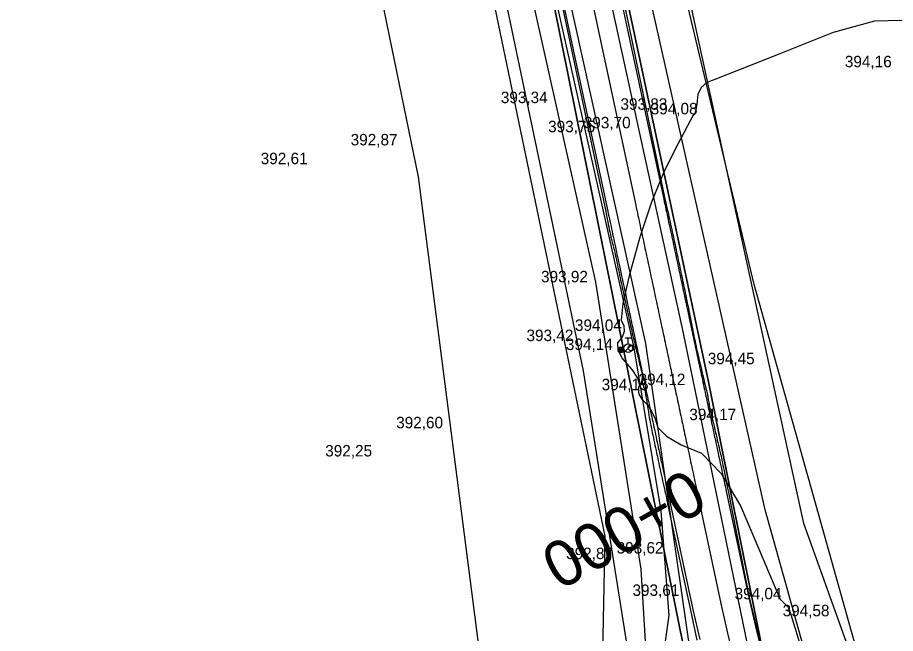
# Model space of a CAD drawing. Extents: x -574342 to -507939, y -1144044 to -1123894.
# Drawn here: x -508564.2 to -508487.6, y -1143040.7 to -1142986.9 of the extents above; entities that cross this region are included whole.
import ezdxf

# ---------------------------------------------------------------- set-up
doc = ezdxf.new("R2010")
doc.units = 0
for name, color, linetype in [('01_PARCELY_NAVRH_PC', 7, 'Continuous'), ('01_PARCELY_NAVRH_ŽP', 7, 'Continuous'), ('07_VODOVOD', 7, 'Continuous'), ('1000', 7, 'Continuous'), ('18', 7, 'Continuous'), ('21', 7, 'Continuous'), ('37', 7, 'Continuous'), ('42', 7, 'Continuous'), ('52', 7, 'Continuous'), ('55', 7, 'Continuous'), ('6', 7, 'Continuous'), ('Level 255', 7, 'Continuous'), ('VRST VEDL', 7, 'Continuous')]:
    doc.layers.add(name, color=color, linetype=linetype)

msp = doc.modelspace()

# ---------------------------------------------------------------- linework, layer by layer
at = {"layer": '01_PARCELY_NAVRH_PC'}
msp.add_lwpolyline([(-508546.584, -1142847.7), (-508527.76, -1142936.34), (-508528.85, -1142941.84), (-508524.62, -1142962.65), (-508521.23, -1142966.97), (-508506.03, -1143042.25), (-508499.26, -1143041.98), (-508503.94, -1143018.7), (-508540.355, -1142847.7)], dxfattribs=at)
at = {"layer": '01_PARCELY_NAVRH_ŽP'}
for points in [[(-508551.381, -1142847.7), (-508513, -1143032.18), (-508513.37, -1143051.16), (-508506.03, -1143042.25), (-508521.23, -1142966.97), (-508524.62, -1142962.65), (-508528.85, -1142941.84), (-508527.76, -1142936.34), (-508546.584, -1142847.7)], [(-508540.355, -1142847.7), (-508503.94, -1143018.7), (-508499.26, -1143041.98), (-508491.15, -1143065.29), (-508474.05, -1143124.14), (-508467.92, -1143139.18), (-508459.97, -1143152.33), (-508456.09, -1143158.71), (-508451.57, -1143168.14), (-508437.66, -1143207.58), (-508425.52, -1143241.92), (-508422.7, -1143249.88), (-508420.04, -1143252.1), (-508417.38, -1143252.95), (-508415.56, -1143252.78), (-508448.24, -1143160.16), (-508453.75, -1143145.01), (-508465.11, -1143123.03), (-508471.48, -1143106.99), (-508484.55, -1143061.98), (-508495.62, -1143031.06), (-508523.23, -1142904.28), (-508534.61, -1142847.7)]]:
    msp.add_lwpolyline(points, dxfattribs=at)
at = {"layer": '07_VODOVOD'}
msp.add_lwpolyline([(-508640.05, -1143130.18), (-508637.48, -1143128.83), (-508626.48, -1143135.95), (-508617.09, -1143140.73), (-508602.61, -1143146.08), (-508586.87, -1143149.65), (-508578.03, -1143148.66), (-508571.02, -1143145.86), (-508562.51, -1143139.92), (-508546.01, -1143124.95), (-508535.68, -1143117.17), (-508526.75, -1143109.24), (-508521.13, -1143103.37), (-508515.47, -1143095.19), (-508511.95, -1143085.3), (-508511.14, -1143074.49), (-508510.31, -1143059.6), (-508507.36, -1143039.1), (-508508.06, -1143029.96), (-508510.42, -1143015.75), (-508519.77, -1142974.08), (-508526.08, -1142944.88), (-508540.82, -1142875.36), (-508546.434, -1142847.7)], dxfattribs=at)
at = {"layer": '1000'}
for points in [[(-508512.952, -1142978.88), (-508507.844, -1143002.764), (-508507.797, -1143002.986), (-508507.749, -1143003.208), (-508507.702, -1143003.429), (-508507.655, -1143003.651), (-508507.607, -1143003.873), (-508507.56, -1143004.094), (-508507.512, -1143004.316), (-508507.465, -1143004.538), (-508507.418, -1143004.759), (-508507.37, -1143004.981), (-508507.323, -1143005.203), (-508507.275, -1143005.424), (-508507.228, -1143005.646), (-508507.181, -1143005.868), (-508507.133, -1143006.089), (-508507.086, -1143006.311), (-508507.038, -1143006.533), (-508506.991, -1143006.754), (-508506.944, -1143006.976), (-508506.896, -1143007.198), (-508506.849, -1143007.419), (-508506.801, -1143007.641), (-508506.754, -1143007.863), (-508506.707, -1143008.084), (-508506.659, -1143008.306), (-508506.612, -1143008.528), (-508506.564, -1143008.749), (-508506.517, -1143008.971), (-508506.469, -1143009.193), (-508506.422, -1143009.414), (-508506.375, -1143009.636), (-508506.327, -1143009.858), (-508506.28, -1143010.079), (-508506.232, -1143010.301), (-508506.185, -1143010.523), (-508506.138, -1143010.744), (-508506.09, -1143010.966), (-508506.043, -1143011.188), (-508505.995, -1143011.409), (-508505.948, -1143011.631), (-508505.901, -1143011.853), (-508505.853, -1143012.074), (-508505.806, -1143012.296), (-508505.758, -1143012.518), (-508505.711, -1143012.739), (-508505.664, -1143012.961), (-508505.616, -1143013.183), (-508505.569, -1143013.404), (-508505.521, -1143013.626), (-508505.474, -1143013.848), (-508505.427, -1143014.069), (-508505.379, -1143014.291), (-508505.332, -1143014.513), (-508505.284, -1143014.734), (-508505.237, -1143014.956), (-508505.19, -1143015.178), (-508505.142, -1143015.399), (-508505.095, -1143015.621), (-508505.047, -1143015.842), (-508505, -1143016.064), (-508504.953, -1143016.286), (-508504.905, -1143016.507), (-508504.858, -1143016.729), (-508504.81, -1143016.951), (-508504.763, -1143017.172), (-508504.716, -1143017.394), (-508504.668, -1143017.616), (-508504.621, -1143017.837), (-508504.573, -1143018.059), (-508504.526, -1143018.281), (-508504.479, -1143018.502), (-508504.431, -1143018.724), (-508504.384, -1143018.946), (-508504.336, -1143019.167), (-508504.289, -1143019.389), (-508504.241, -1143019.611), (-508504.194, -1143019.832), (-508504.147, -1143020.054), (-508504.099, -1143020.276), (-508504.052, -1143020.497), (-508504.004, -1143020.719), (-508503.957, -1143020.941), (-508503.91, -1143021.162), (-508503.862, -1143021.384), (-508503.815, -1143021.606), (-508503.767, -1143021.827), (-508503.72, -1143022.049), (-508503.673, -1143022.271), (-508503.625, -1143022.492), (-508503.578, -1143022.714), (-508503.53, -1143022.936), (-508503.483, -1143023.157), (-508503.436, -1143023.379), (-508503.388, -1143023.601), (-508503.341, -1143023.822), (-508503.293, -1143024.044), (-508503.246, -1143024.266), (-508503.199, -1143024.487), (-508503.151, -1143024.709), (-508503.104, -1143024.931), (-508503.056, -1143025.152), (-508503.009, -1143025.374), (-508502.962, -1143025.596), (-508502.914, -1143025.817), (-508502.867, -1143026.039), (-508502.819, -1143026.261), (-508502.772, -1143026.482), (-508502.725, -1143026.704), (-508502.677, -1143026.926), (-508502.63, -1143027.147), (-508502.582, -1143027.369), (-508502.535, -1143027.591), (-508502.496, -1143027.774), (-508502.488, -1143027.812), (-508502.44, -1143028.034), (-508502.393, -1143028.256), (-508500.408, -1143037.538), (-508499.842, -1143040.075), (-508499.33, -1143042.206)], [(-508512.721, -1142978.831), (-508507.743, -1143002.743), (-508507.693, -1143002.964), (-508507.643, -1143003.185), (-508507.593, -1143003.406), (-508507.544, -1143003.627), (-508507.494, -1143003.849), (-508507.444, -1143004.07), (-508507.395, -1143004.291), (-508507.346, -1143004.512), (-508507.297, -1143004.734), (-508507.249, -1143004.955), (-508507.2, -1143005.177), (-508507.152, -1143005.398), (-508507.104, -1143005.619), (-508507.055, -1143005.841), (-508507.007, -1143006.062), (-508506.959, -1143006.284), (-508506.911, -1143006.506), (-508506.863, -1143006.727), (-508506.816, -1143006.949), (-508506.768, -1143007.17), (-508506.721, -1143007.392), (-508506.673, -1143007.614), (-508506.626, -1143007.835), (-508506.579, -1143008.057), (-508506.531, -1143008.279), (-508506.484, -1143008.5), (-508506.437, -1143008.722), (-508506.391, -1143008.944), (-508506.344, -1143009.166), (-508506.297, -1143009.388), (-508506.251, -1143009.609), (-508506.204, -1143009.831), (-508506.158, -1143010.053), (-508506.112, -1143010.275), (-508506.065, -1143010.497), (-508506.019, -1143010.719), (-508505.973, -1143010.941), (-508505.927, -1143011.163), (-508505.882, -1143011.385), (-508505.836, -1143011.607), (-508505.79, -1143011.829), (-508505.745, -1143012.051), (-508505.7, -1143012.273), (-508505.654, -1143012.495), (-508505.609, -1143012.717), (-508505.564, -1143012.94), (-508505.519, -1143013.162), (-508505.474, -1143013.384), (-508505.429, -1143013.606), (-508505.385, -1143013.828), (-508505.34, -1143014.051), (-508505.296, -1143014.273), (-508505.251, -1143014.495), (-508505.207, -1143014.718), (-508505.163, -1143014.94), (-508505.118, -1143015.162), (-508505.074, -1143015.385), (-508505.031, -1143015.607), (-508504.982, -1143015.829), (-508504.93, -1143016.049), (-508504.877, -1143016.27), (-508504.825, -1143016.49), (-508504.773, -1143016.711), (-508504.721, -1143016.932), (-508504.669, -1143017.152), (-508504.617, -1143017.373), (-508504.565, -1143017.594), (-508504.514, -1143017.815), (-508504.462, -1143018.035), (-508504.411, -1143018.256), (-508504.359, -1143018.477), (-508504.308, -1143018.698), (-508504.255, -1143018.918), (-508504.202, -1143019.139), (-508504.149, -1143019.359), (-508504.096, -1143019.58), (-508504.043, -1143019.8), (-508504.001, -1143020.023), (-508503.961, -1143020.246), (-508503.921, -1143020.469), (-508503.881, -1143020.693), (-508503.841, -1143020.916), (-508503.795, -1143021.138), (-508503.743, -1143021.359), (-508503.691, -1143021.579), (-508503.639, -1143021.8), (-508503.587, -1143022.021), (-508503.535, -1143022.241), (-508503.483, -1143022.462), (-508503.431, -1143022.683), (-508503.38, -1143022.903), (-508503.328, -1143023.124), (-508503.277, -1143023.345), (-508503.225, -1143023.566), (-508503.174, -1143023.787), (-508503.123, -1143024.008), (-508503.072, -1143024.228), (-508503.021, -1143024.449), (-508502.97, -1143024.67), (-508502.919, -1143024.891), (-508502.869, -1143025.112), (-508502.818, -1143025.333), (-508502.768, -1143025.554), (-508502.722, -1143025.776), (-508502.677, -1143025.998), (-508502.632, -1143026.221), (-508502.587, -1143026.443), (-508502.542, -1143026.665), (-508502.498, -1143026.887), (-508502.453, -1143027.11), (-508502.409, -1143027.332), (-508502.365, -1143027.554), (-508502.328, -1143027.738), (-508502.32, -1143027.776), (-508502.276, -1143027.999), (-508502.232, -1143028.221), (-508500.389, -1143037.534), (-508499.796, -1143040.064), (-508499.262, -1143042.19)], [(-508517.956, -1142979.95), (-508512.913, -1143003.849), (-508512.87, -1143004.071), (-508512.826, -1143004.293), (-508512.782, -1143004.516), (-508512.738, -1143004.738), (-508512.694, -1143004.961), (-508512.649, -1143005.183), (-508512.605, -1143005.405), (-508512.561, -1143005.627), (-508512.507, -1143005.848), (-508512.453, -1143006.068), (-508512.399, -1143006.288), (-508512.344, -1143006.508), (-508512.289, -1143006.728), (-508512.235, -1143006.949), (-508512.18, -1143007.169), (-508512.125, -1143007.389), (-508512.075, -1143007.61), (-508512.029, -1143007.832), (-508511.982, -1143008.054), (-508511.935, -1143008.275), (-508511.889, -1143008.497), (-508511.842, -1143008.719), (-508511.795, -1143008.941), (-508511.748, -1143009.162), (-508511.701, -1143009.384), (-508511.653, -1143009.606), (-508511.606, -1143009.828), (-508511.558, -1143010.049), (-508511.511, -1143010.271), (-508511.463, -1143010.492), (-508511.415, -1143010.714), (-508511.367, -1143010.936), (-508511.319, -1143011.157), (-508511.271, -1143011.379), (-508511.223, -1143011.6), (-508511.175, -1143011.821), (-508511.126, -1143012.043), (-508511.078, -1143012.264), (-508511.029, -1143012.486), (-508510.98, -1143012.707), (-508510.932, -1143012.928), (-508510.883, -1143013.15), (-508510.834, -1143013.371), (-508510.784, -1143013.592), (-508510.735, -1143013.814), (-508510.686, -1143014.035), (-508510.636, -1143014.256), (-508510.591, -1143014.478), (-508510.54, -1143014.699), (-508510.488, -1143014.92), (-508510.436, -1143015.14), (-508510.383, -1143015.361), (-508510.329, -1143015.581), (-508510.276, -1143015.802), (-508510.222, -1143016.022), (-508510.168, -1143016.242), (-508510.115, -1143016.463), (-508510.061, -1143016.683), (-508510.007, -1143016.903), (-508509.953, -1143017.123), (-508509.899, -1143017.344), (-508509.845, -1143017.564), (-508509.79, -1143017.784), (-508509.736, -1143018.004), (-508509.733, -1143018.235), (-508509.738, -1143018.468), (-508509.719, -1143018.696), (-508509.659, -1143018.915), (-508509.599, -1143019.134), (-508509.538, -1143019.353), (-508509.478, -1143019.572), (-508509.436, -1143019.795), (-508509.401, -1143020.019), (-508509.365, -1143020.243), (-508509.329, -1143020.467), (-508509.292, -1143020.691), (-508509.256, -1143020.915), (-508509.22, -1143021.139), (-508509.183, -1143021.363), (-508509.147, -1143021.587), (-508509.11, -1143021.811), (-508509.073, -1143022.035), (-508509.032, -1143022.258), (-508508.986, -1143022.48), (-508508.94, -1143022.702), (-508508.894, -1143022.924), (-508508.847, -1143023.146), (-508508.801, -1143023.367), (-508508.754, -1143023.589), (-508508.707, -1143023.811), (-508508.66, -1143024.033), (-508508.613, -1143024.254), (-508508.566, -1143024.476), (-508508.519, -1143024.698), (-508508.471, -1143024.92), (-508508.424, -1143025.141), (-508508.376, -1143025.363), (-508508.328, -1143025.584), (-508508.28, -1143025.806), (-508508.232, -1143026.027), (-508508.184, -1143026.249), (-508508.136, -1143026.47), (-508508.087, -1143026.692), (-508508.039, -1143026.913), (-508507.99, -1143027.135), (-508507.942, -1143027.356), (-508507.893, -1143027.577), (-508507.844, -1143027.799), (-508507.795, -1143028.02), (-508507.745, -1143028.241), (-508507.696, -1143028.463), (-508507.646, -1143028.684), (-508507.607, -1143028.867), (-508507.599, -1143028.905), (-508507.553, -1143029.127), (-508507.508, -1143029.35), (-508505.499, -1143038.627), (-508504.958, -1143041.264)], [(-508517.842, -1142979.926), (-508512.734, -1143003.81), (-508512.686, -1143004.032), (-508512.639, -1143004.253), (-508512.591, -1143004.475), (-508512.544, -1143004.697), (-508512.497, -1143004.918), (-508512.449, -1143005.14), (-508512.402, -1143005.362), (-508512.354, -1143005.583), (-508512.307, -1143005.805), (-508512.26, -1143006.027), (-508512.212, -1143006.248), (-508512.165, -1143006.47), (-508512.117, -1143006.692), (-508512.07, -1143006.913), (-508512.023, -1143007.135), (-508511.975, -1143007.357), (-508511.928, -1143007.578), (-508511.88, -1143007.8), (-508511.833, -1143008.022), (-508511.786, -1143008.243), (-508511.738, -1143008.465), (-508511.691, -1143008.687), (-508511.643, -1143008.908), (-508511.596, -1143009.13), (-508511.549, -1143009.352), (-508511.501, -1143009.573), (-508511.454, -1143009.795), (-508511.406, -1143010.017), (-508511.359, -1143010.238), (-508511.312, -1143010.46), (-508511.264, -1143010.682), (-508511.217, -1143010.903), (-508511.169, -1143011.125), (-508511.122, -1143011.347), (-508511.075, -1143011.568), (-508511.027, -1143011.79), (-508510.98, -1143012.012), (-508510.932, -1143012.233), (-508510.885, -1143012.455), (-508510.837, -1143012.677), (-508510.79, -1143012.898), (-508510.743, -1143013.12), (-508510.695, -1143013.342), (-508510.648, -1143013.563), (-508510.6, -1143013.785), (-508510.553, -1143014.007), (-508510.506, -1143014.228), (-508510.458, -1143014.45), (-508510.411, -1143014.672), (-508510.363, -1143014.893), (-508510.316, -1143015.115), (-508510.269, -1143015.337), (-508510.221, -1143015.558), (-508510.174, -1143015.78), (-508510.126, -1143016.002), (-508510.079, -1143016.223), (-508510.032, -1143016.445), (-508509.984, -1143016.666), (-508509.937, -1143016.888), (-508509.889, -1143017.11), (-508509.842, -1143017.331), (-508509.795, -1143017.553), (-508509.747, -1143017.775), (-508509.7, -1143017.996), (-508509.652, -1143018.218), (-508509.605, -1143018.44), (-508509.558, -1143018.661), (-508509.51, -1143018.883), (-508509.463, -1143019.105), (-508509.415, -1143019.326), (-508509.368, -1143019.548), (-508509.321, -1143019.77), (-508509.273, -1143019.991), (-508509.226, -1143020.213), (-508509.178, -1143020.435), (-508509.131, -1143020.656), (-508509.084, -1143020.878), (-508509.036, -1143021.1), (-508508.989, -1143021.321), (-508508.941, -1143021.543), (-508508.894, -1143021.765), (-508508.846, -1143021.986), (-508508.799, -1143022.208), (-508508.752, -1143022.43), (-508508.704, -1143022.651), (-508508.657, -1143022.873), (-508508.609, -1143023.095), (-508508.562, -1143023.316), (-508508.515, -1143023.538), (-508508.467, -1143023.76), (-508508.42, -1143023.981), (-508508.372, -1143024.203), (-508508.325, -1143024.425), (-508508.278, -1143024.646), (-508508.23, -1143024.868), (-508508.183, -1143025.09), (-508508.135, -1143025.311), (-508508.088, -1143025.533), (-508508.041, -1143025.755), (-508507.993, -1143025.976), (-508507.946, -1143026.198), (-508507.898, -1143026.42), (-508507.851, -1143026.641), (-508507.804, -1143026.863), (-508507.756, -1143027.085), (-508507.709, -1143027.306), (-508507.661, -1143027.528), (-508507.614, -1143027.75), (-508507.567, -1143027.971), (-508507.519, -1143028.193), (-508507.472, -1143028.415), (-508507.424, -1143028.636), (-508507.385, -1143028.82), (-508507.377, -1143028.858), (-508507.33, -1143029.08), (-508507.282, -1143029.301), (-508505.297, -1143038.583), (-508504.712, -1143041.207)]]:
    msp.add_lwpolyline(points, dxfattribs=at)
at = {"layer": '21'}
msp.add_lwpolyline([(-508515.397, -1142979.403), (-508510.289, -1143003.287), (-508510.242, -1143003.509), (-508510.194, -1143003.731), (-508510.147, -1143003.952), (-508510.099, -1143004.174), (-508510.052, -1143004.396), (-508510.005, -1143004.617), (-508509.957, -1143004.839), (-508509.91, -1143005.061), (-508509.862, -1143005.282), (-508509.815, -1143005.504), (-508509.768, -1143005.726), (-508509.72, -1143005.947), (-508509.673, -1143006.169), (-508509.625, -1143006.391), (-508509.578, -1143006.612), (-508509.53, -1143006.834), (-508509.483, -1143007.056), (-508509.436, -1143007.277), (-508509.388, -1143007.499), (-508509.341, -1143007.721), (-508509.293, -1143007.942), (-508509.246, -1143008.164), (-508509.199, -1143008.385), (-508509.151, -1143008.607), (-508509.104, -1143008.829), (-508509.056, -1143009.05), (-508509.009, -1143009.272), (-508508.962, -1143009.494), (-508508.914, -1143009.715), (-508508.867, -1143009.937), (-508508.819, -1143010.159), (-508508.772, -1143010.38), (-508508.725, -1143010.602), (-508508.677, -1143010.824), (-508508.63, -1143011.045), (-508508.582, -1143011.267), (-508508.535, -1143011.489), (-508508.488, -1143011.71), (-508508.44, -1143011.932), (-508508.393, -1143012.154), (-508508.345, -1143012.375), (-508508.298, -1143012.597), (-508508.251, -1143012.819), (-508508.203, -1143013.04), (-508508.156, -1143013.262), (-508508.108, -1143013.484), (-508508.061, -1143013.705), (-508508.014, -1143013.927), (-508507.966, -1143014.149), (-508507.919, -1143014.37), (-508507.871, -1143014.592), (-508507.824, -1143014.814), (-508507.777, -1143015.035), (-508507.729, -1143015.257), (-508507.682, -1143015.479), (-508507.634, -1143015.7), (-508507.587, -1143015.922), (-508507.539, -1143016.144), (-508507.492, -1143016.365), (-508507.445, -1143016.587), (-508507.397, -1143016.809), (-508507.35, -1143017.03), (-508507.302, -1143017.252), (-508507.255, -1143017.474), (-508507.208, -1143017.695), (-508507.16, -1143017.917), (-508507.113, -1143018.139), (-508507.065, -1143018.36), (-508507.018, -1143018.582), (-508506.971, -1143018.804), (-508506.923, -1143019.025), (-508506.876, -1143019.247), (-508506.828, -1143019.469), (-508506.781, -1143019.69), (-508506.734, -1143019.912), (-508506.686, -1143020.134), (-508506.639, -1143020.355), (-508506.591, -1143020.577), (-508506.544, -1143020.799), (-508506.497, -1143021.02), (-508506.449, -1143021.242), (-508506.402, -1143021.464), (-508506.354, -1143021.685), (-508506.307, -1143021.907), (-508506.26, -1143022.129), (-508506.212, -1143022.35), (-508506.165, -1143022.572), (-508506.117, -1143022.794), (-508506.07, -1143023.015), (-508506.023, -1143023.237), (-508505.975, -1143023.459), (-508505.928, -1143023.68), (-508505.88, -1143023.902), (-508505.833, -1143024.123), (-508505.786, -1143024.345), (-508505.738, -1143024.567), (-508505.691, -1143024.788), (-508505.643, -1143025.01), (-508505.596, -1143025.232), (-508505.548, -1143025.453), (-508505.501, -1143025.675), (-508505.454, -1143025.897), (-508505.406, -1143026.118), (-508505.359, -1143026.34), (-508505.311, -1143026.562), (-508505.264, -1143026.783), (-508505.217, -1143027.005), (-508505.169, -1143027.227), (-508505.122, -1143027.448), (-508505.074, -1143027.67), (-508505.027, -1143027.892), (-508504.98, -1143028.113), (-508504.94, -1143028.297), (-508504.932, -1143028.335), (-508504.885, -1143028.557), (-508504.837, -1143028.778), (-508502.852, -1143038.061), (-508502.277, -1143040.641), (-508501.756, -1143042.808)], dxfattribs=at)
at = {"layer": '37'}
for points in [[(-508511.59, -1143124.92), (-508509.54, -1143119.35), (-508506.51, -1143105.44), (-508506, -1143084.25), (-508505.31, -1143056.58), (-508505.39, -1143050.71), (-508505.49, -1143042.55), (-508509.4, -1143015.37), (-508521.08, -1142962.59), (-508532.6, -1142908.81), (-508545.204, -1142847.7)], [(-508511.59, -1143124.92), (-508509.54, -1143119.35), (-508506.51, -1143105.44), (-508506, -1143084.25), (-508505.31, -1143056.58), (-508505.39, -1143050.71), (-508505.49, -1143042.55), (-508509.4, -1143015.37), (-508521.08, -1142962.59), (-508532.6, -1142908.81), (-508545.204, -1142847.7)], [(-508541.866, -1142847.7), (-508529.22, -1142908.11), (-508517.67, -1142961.7), (-508506.14, -1143014.46), (-508500.54, -1143041.74), (-508495.34, -1143058.46)], [(-508541.866, -1142847.7), (-508529.22, -1142908.11), (-508517.67, -1142961.7), (-508506.14, -1143014.46), (-508500.54, -1143041.74), (-508495.34, -1143058.46)]]:
    msp.add_lwpolyline(points, dxfattribs=at)
at = {"layer": '42'}
for points in [[(-508560.651, -1142847.7), (-508548.46, -1142911.06), (-508536.86, -1142963.87), (-508529.29, -1143000.8), (-508523.32, -1143047.2)], [(-508560.651, -1142847.7), (-508548.46, -1142911.06), (-508536.86, -1142963.87), (-508529.29, -1143000.8), (-508523.32, -1143047.2)], [(-508510.77, -1143053.59), (-508510.65, -1143044.07), (-508514.85, -1143017.75), (-508526.24, -1142963.32), (-508538.39, -1142909.19), (-508550.685, -1142847.7)], [(-508510.77, -1143053.59), (-508510.65, -1143044.07), (-508514.85, -1143017.75), (-508526.24, -1142963.32), (-508538.39, -1142909.19), (-508550.685, -1142847.7)], [(-508445.89, -1143059.01), (-508479.63, -1143062.18), (-508484.42, -1143059.76), (-508487.39, -1143055.01), (-508499.96, -1143010.2), (-508511.4, -1142962.16), (-508523.74, -1142906.21), (-508535.517, -1142847.7)], [(-508445.89, -1143059.01), (-508479.63, -1143062.18), (-508484.42, -1143059.76), (-508487.39, -1143055.01), (-508499.96, -1143010.2), (-508511.4, -1142962.16), (-508523.74, -1142906.21), (-508535.517, -1142847.7)]]:
    msp.add_lwpolyline(points, dxfattribs=at)
at = {"layer": '52'}
for p, q in [((-508511.2, -1143014.87), (-508510.7, -1143014.87)), ((-508510.95, -1143015.395), (-508510.95, -1143014.87)), ((-508511.215, -1143016.035), (-508510.685, -1143015.505))]:
    msp.add_line(p, q, dxfattribs=at)
for centre, radius in [((-508511.58, -1143015.91), 0.25), ((-508510.95, -1143015.77), 0.375), ((-508510.7, -1143015.75), 0.25), ((-508511.58, -1143015.91), 0.158), ((-508511.58, -1143015.91), 0.05)]:
    msp.add_circle(centre, radius, dxfattribs=at)
at = {"layer": '55'}
for points in [[(-508548.593, -1142847.7), (-508536.61, -1142907.95), (-508524.27, -1142963.1), (-508513.79, -1143010.01), (-508509.84, -1143035.05), (-508508.31, -1143060.76)], [(-508548.593, -1142847.7), (-508536.61, -1142907.95), (-508524.27, -1142963.1), (-508513.79, -1143010.01), (-508509.84, -1143035.05), (-508508.31, -1143060.76)], [(-508492.58, -1143052.86), (-508498.99, -1143029.87), (-508513.85, -1142963.71), (-508525.48, -1142909.41), (-508538.364, -1142847.7)], [(-508492.58, -1143052.86), (-508498.99, -1143029.87), (-508513.85, -1142963.71), (-508525.48, -1142909.41), (-508538.364, -1142847.7)]]:
    msp.add_lwpolyline(points, dxfattribs=at)
at = {"layer": '6'}
msp.add_lwpolyline([(-508504.94, -1143028.297), (-508504.94, -1143028.297)], dxfattribs=at)
at = {"layer": 'VRST VEDL'}
msp.add_lwpolyline([(-508487.077, -1142987.165), (-508489.456, -1142987.218), (-508493.055, -1142988.211), (-508497.874, -1142990.143), (-508501.319, -1142991.516), (-508503.391, -1142992.329), (-508504.088, -1142992.582), (-508504.581, -1142993.017), (-508504.872, -1142993.634), (-508504.958, -1142994.433), (-508505.059, -1142995.008), (-508505.173, -1142995.36), (-508505.301, -1142995.489), (-508505.782, -1142996.36), (-508506.615, -1142997.975), (-508507.8, -1143000.332), (-508508.902, -1143003.033), (-508509.922, -1143006.076), (-508510.859, -1143009.461), (-508511.405, -1143011.882), (-508511.559, -1143013.337), (-508511.321, -1143013.827), (-508511.294, -1143014.316), (-508511.478, -1143014.804), (-508511.874, -1143015.291), (-508511.866, -1143015.925), (-508511.455, -1143016.705), (-508510.642, -1143017.632), (-508510.142, -1143018.383), (-508509.957, -1143018.959), (-508510.086, -1143019.36), (-508510.02, -1143019.784), (-508509.758, -1143020.23), (-508509.301, -1143020.699), (-508508.914, -1143021.267), (-508508.599, -1143021.936), (-508508.354, -1143022.704), (-508507.6, -1143023.458), (-508506.336, -1143024.198), (-508504.563, -1143024.923), (-508502.833, -1143026.702), (-508501.146, -1143029.535), (-508499.503, -1143033.422), (-508498.391, -1143036.053), (-508497.81, -1143037.427), (-508497.759, -1143037.544), (-508497.648, -1143037.7), (-508497.476, -1143037.892), (-508497.243, -1143038.123), (-508497.078, -1143038.287), (-508496.981, -1143038.385), (-508496.953, -1143038.418), (-508496.759, -1143039.009), (-508496.401, -1143040.16), (-508495.877, -1143041.869)], dxfattribs=at)

# ---------------------------------------------------------------- texts
at = {"layer": '18'}
msp.add_text('0+000', height=4, rotation=208.9664, dxfattribs=at).set_placement((-508505.738, -1143026.178))
at = {"layer": 'Level 255'}
for s, p in [('394,16', (-508492.045, -1142991.25)), ('393,34', (-508522.065, -1142994.38)), ('393,83', (-508511.625, -1142994.96)), ('394,08', (-508508.985, -1142995.36)), ('393,70', (-508514.825, -1142996.58)), ('393,75', (-508517.935, -1142996.92)), ('392,87', (-508535.165, -1142998.07)), ('392,61', (-508543.015, -1142999.71)), ('393,92', (-508518.555, -1143010.02)), ('394,04', (-508515.595, -1143014.26)), ('393,42', (-508519.825, -1143015.15)), ('394,14', (-508516.385, -1143015.93)), ('394,45', (-508504.005, -1143017.17)), ('394,12', (-508510.045, -1143018.99)), ('394,15', (-508513.265, -1143019.44)), ('394,17', (-508505.615, -1143022.05)), ('392,60', (-508531.195, -1143022.76)), ('392,25', (-508537.385, -1143025.22)), ('392,87', (-508516.365, -1143034.18)), ('393,62', (-508511.955, -1143033.69)), ('393,61', (-508510.575, -1143037.39)), ('394,04', (-508501.665, -1143037.69)), ('394,58', (-508497.475, -1143039.17))]:
    msp.add_text(s, height=1, dxfattribs=at).set_placement(p)

doc.saveas('drawing.dxf')
